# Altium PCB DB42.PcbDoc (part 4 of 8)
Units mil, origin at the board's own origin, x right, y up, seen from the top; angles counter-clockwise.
Board outline 3236.22 x 4456.69 mil, 8 copper layers (Top Layer, MidLayer1, MidLayer2, GND-Layer5, MidLayer3, VCC, MidLayer4, Bottom Layer), stack 62.194 mil thick; 214 components, 470 nets, 1802 pads, 1663 vias.
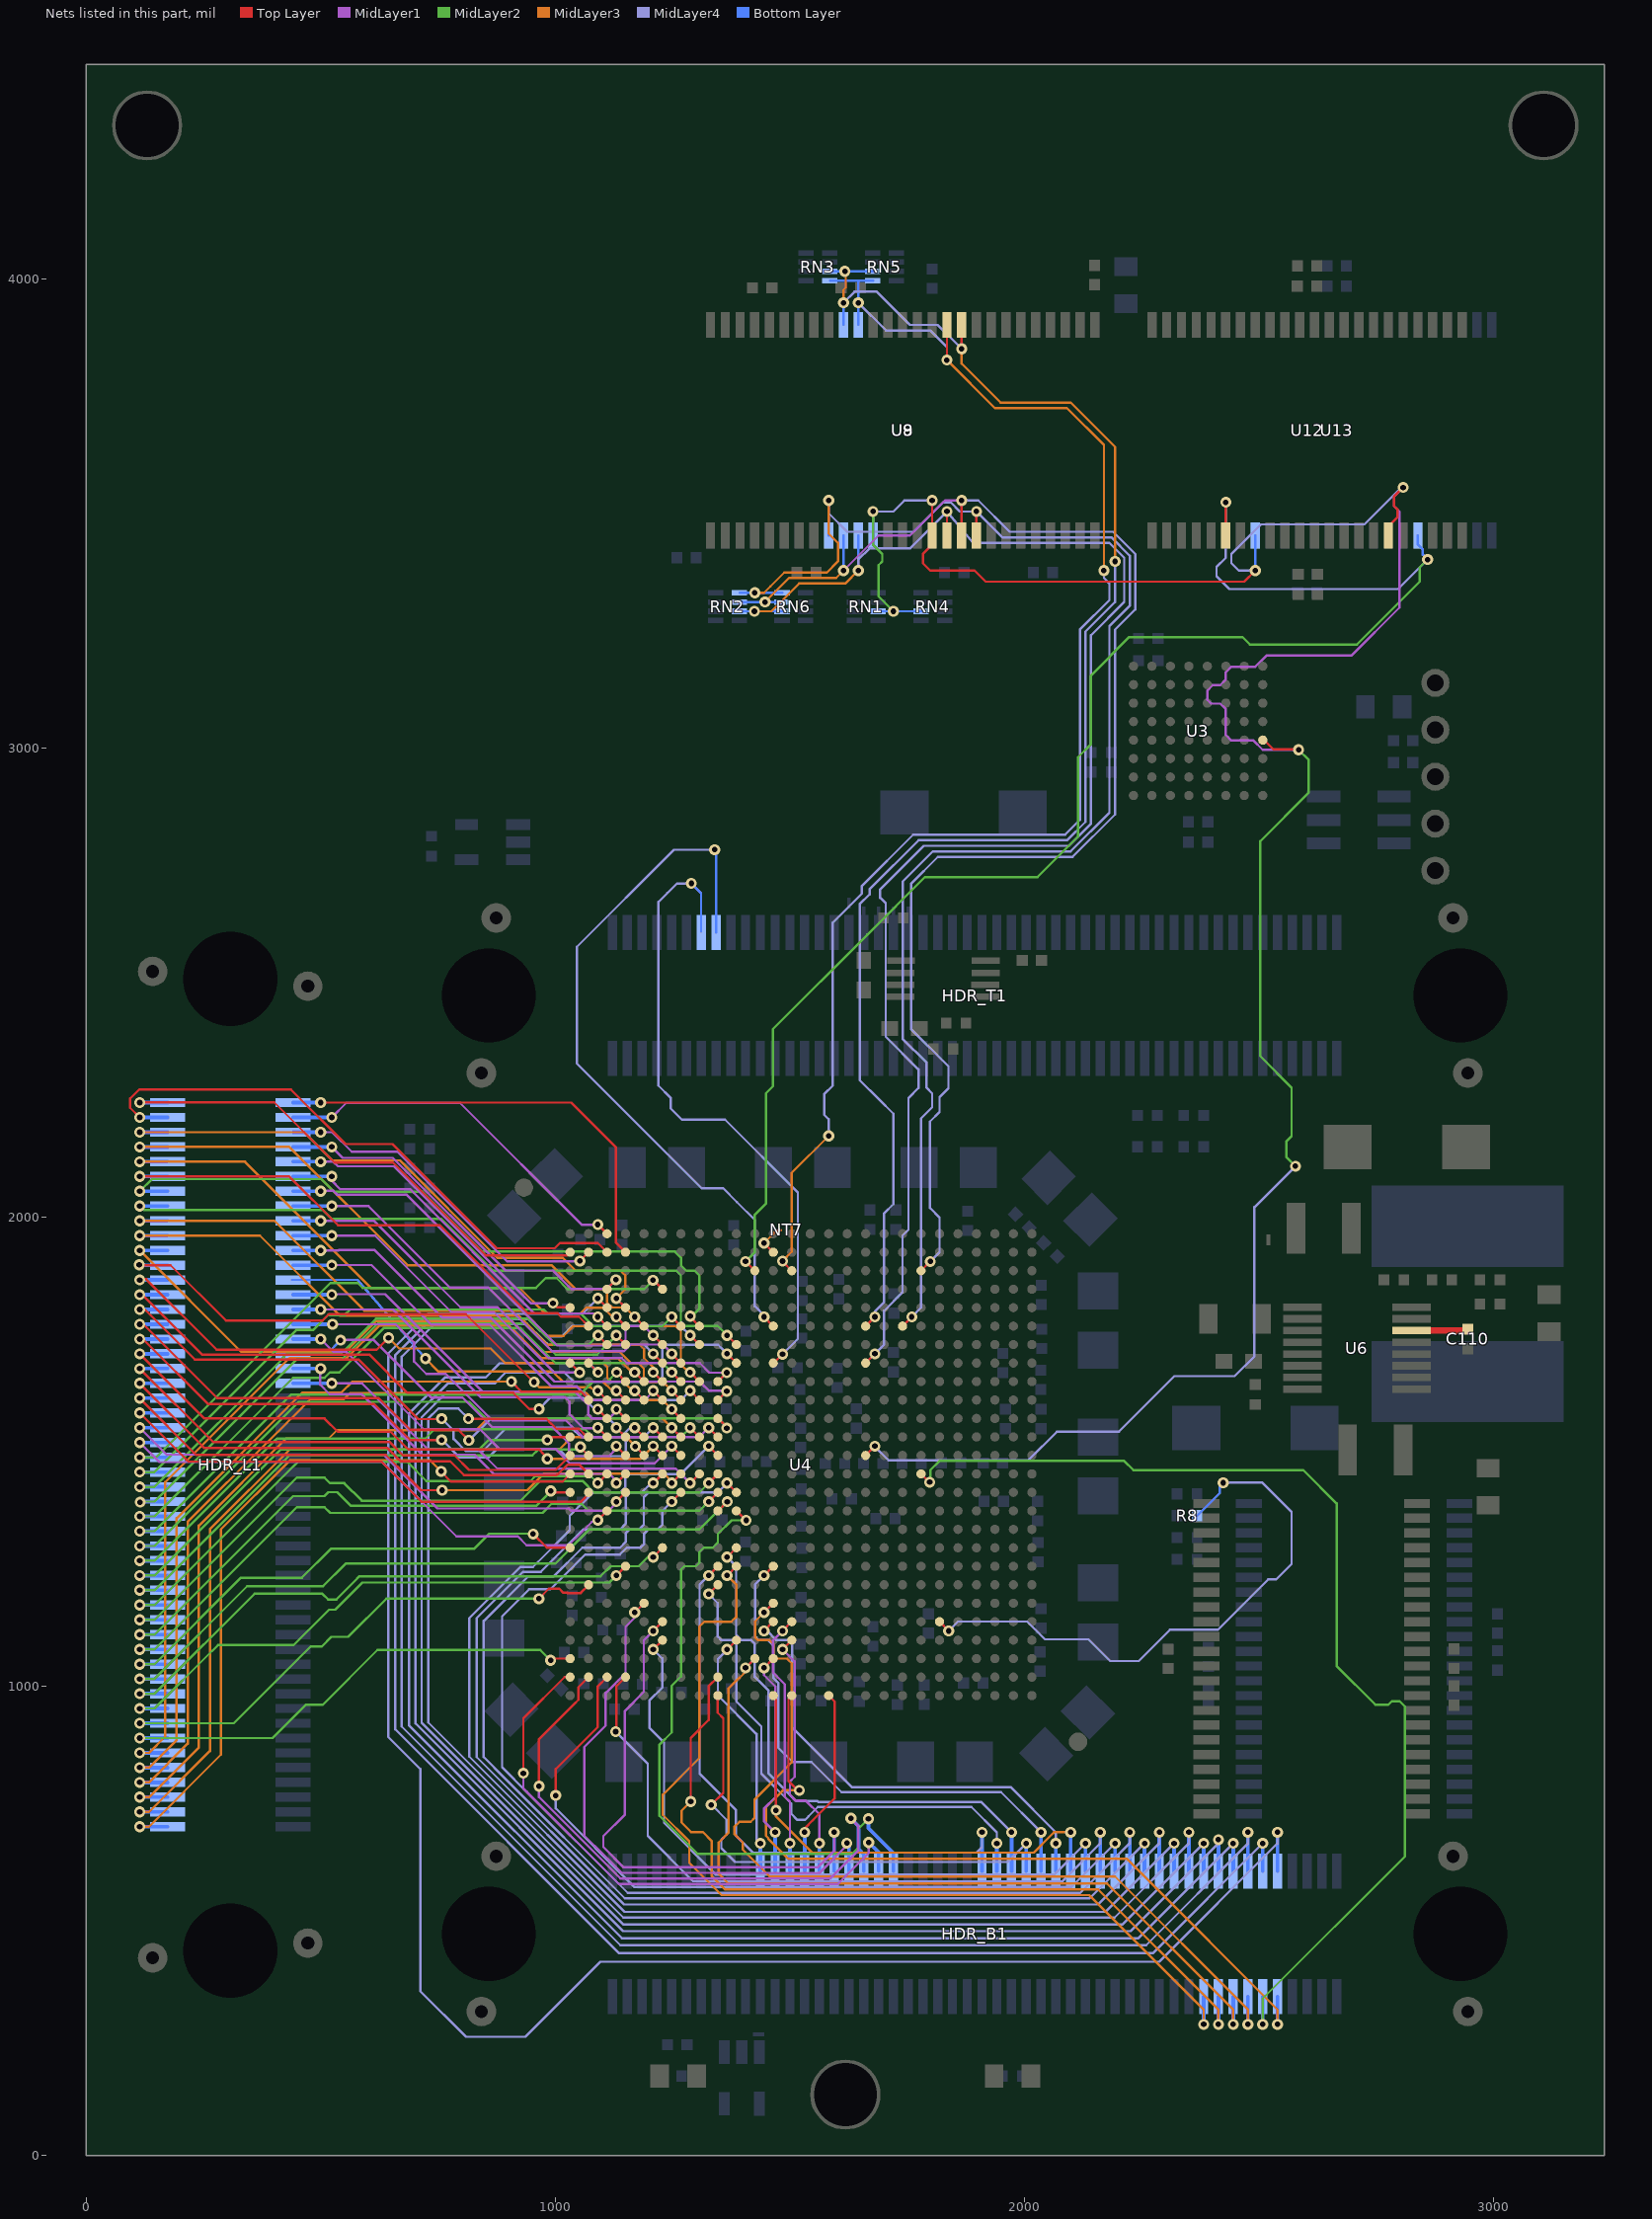
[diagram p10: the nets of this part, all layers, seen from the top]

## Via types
v1: diameter 23.62, hole 11.81, Top Layer to Bottom Layer, 1081 vias
v2: diameter 23.62, hole 11.81, Top Layer to Bottom Layer, tented both sides, 466 vias
v3: diameter 27.56, hole 15.75, Top Layer to Bottom Layer, 116 vias

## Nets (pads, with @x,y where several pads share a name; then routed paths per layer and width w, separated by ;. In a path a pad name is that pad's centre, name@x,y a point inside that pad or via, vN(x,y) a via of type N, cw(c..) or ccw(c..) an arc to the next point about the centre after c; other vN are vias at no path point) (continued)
BUS_NWE: RN1.7 RN4.6 U3.A5 U4.N17 U8.16 U9.16 U12.17 U13.17 | length 5598.1
  Top Layer w5: U4.N17@1661.42,1492.13 v1(1681.1,1511.81) ; U8.16@1803.14,3452.75 v2(1803.14,3527.55) ; U8.16@1803.15,3460.62 1803.15,3433.07 1783.46,3413.39 1783.46,3393.7 1799.21,3377.95 1893.7,3377.95 1917.32,3354.33 2468.5,3354.33 v1(2492.13,3377.95) ; U3.A5@2507.87,3016.73 2510.82,3016.74 2530.31,2997.24 v1@2583.46,2997.24 ; v1@2582.28,2998.03 v1(2584.25,2996.06) ; U12.17@2775.59,3452.76 2775.59,3472.44 2795.28,3492.13 2795.28,3507.87 2787.4,3515.75 2787.4,3535.43 v1(2807.09,3555.12)
  MidLayer1 w5: v1(2584.25,2996.06) 2507.87,2996.06 2488.19,3015.75 2440.94,3015.75 2429.13,3027.56 2429.13,3082.68 2417.32,3094.49 2397.64,3094.49 2389.76,3102.36 2389.76,3122.05 2401.57,3133.86 2417.32,3133.86 2429.13,3145.67 2429.13,3161.42 2440.94,3173.23 2492.13,3173.23 2515.75,3196.85 2696.85,3196.85 2799.21,3299.21 2799.21,3503.94 2787.4,3515.75 2787.4,3535.43 v1(2807.09,3555.12)
  MidLayer2 w5: v2(1677.17,3503.94) 1677.17,3433.07 1696.85,3413.39 1696.85,3397.64 1688.98,3389.76 1688.98,3322.83 v1(1720.47,3291.34) ; v1(2577.56,2108.66) 2557.87,2128.35 2557.87,2161.02 2569.29,2172.44 2569.29,2275.99 2502.31,2342.96 2502.31,2801.13 2605.91,2904.72 2605.91,2974.41 v1(2584.25,2996.06)
  MidLayer4 w5: v2(1677.17,3503.94) 1720.47,3503.94 1744.09,3527.55 v2(1803.14,3527.55) ; v1@1681.1,1510.69 1709.9,1481.89 2008.27,1481.89 2069.29,1542.91 2201.18,1542.91 2319.37,1661.1 2447.92,1661.1 2490.08,1703.26 2490.08,2021.18 v1(2577.56,2108.66) ; v1(2492.13,3377.95) 2456.69,3377.95 2440.94,3393.7 2440.94,3413.39 2503.94,3476.38 2724.41,3476.38 v1@2805.12,3557.09
  Bottom Layer w5: U9.16@1677.17,3452.76 v2(1677.17,3503.94) ; RN1.7@1688.18,3291.34 RN4.6@1779.53,3291.33 RN4.6@1779.92,3291.34 ; v1(2492.13,3377.95) U13.17@2492.13,3452.76
BUS_SDRAM_CKE: RN3.7 RN5.6 U4.F17 U8.37 U9.37 | length 3341.3
  Top Layer w5: U4.F17@1661.42,1767.72 v1(1681.1,1787.4) ; v2(1866.14,3850.39) U8.37@1866.14,3901.57
  MidLayer3 w5: v2(1614.17,3948.82) 1614.17,3976.38 1618.9,3981.11 v1@1618.9,4015.75 ; v2(1866.14,3850.39) 1866.14,3818.9 1948.82,3736.22 2098.43,3736.22 2192.91,3641.73 v1(2192.91,3397.64)
  MidLayer4 w5: v2(1614.17,3948.82) 1637.8,3972.44 1685.04,3972.44 1755.91,3901.57 1814.96,3901.57 v2(1866.14,3850.39) ; v1(1681.1,1787.4) 1681.1,1799.31 1700.79,1819 1700.79,1925.59 1700.89,1925.69 1700.89,2008.37 1720.47,2027.95 1720.47,2220.47 1689.76,2251.18 1648.82,2292.12 1648.82,2666.9 1669.68,2687.76 1669.68,2698.43 1774.41,2803.15 2090.55,2803.15 2129.92,2842.52 2129.92,3248.03 2192.91,3311.02 v1(2192.91,3397.64)
  Bottom Layer w5: RN3.7@1586.22,4015.75 v1(1617.14,4015.75) RN5.6@1676.19,4015.75 RN5.6@1677.56,4015.75 ; U9.37@1614.17,3901.57 v2(1614.17,3948.82)
BUS_SDRAM_CLK: NT7.2 RN3.8 RN5.5 U4.C13 U8.38 U9.38 | length 3185.7
  Top Layer w5: v1@1484.25,1905.51 U4.C13@1503.94,1885.83 ; v2(1834.64,3826.77) U8.38@1834.65,3901.57
  MidLayer1 w5: v1(1484.25,1906.3) v1@1485.43,1906.3
  MidLayer3 w5: v1(1484.25,1906.3) 1503.96,1926 1503.96,2094.47 v1(1582.68,2173.23) ; v2(1834.64,3826.77) 1937,3724.41 2090.55,3724.41 2169.29,3645.67 v1(2169.29,3377.95)
  MidLayer4 w5: v1(1582.68,2173.23) 1582.68,2208.66 1573,2218.34 1573,2262 1591.2,2280.2 1591.2,2627.42 1653.54,2689.76 1653.54,2705.91 1762.6,2814.96 2086.61,2814.96 2118.11,2846.46 2118.11,3251.97 2181.1,3314.96 2181.1,3350.39 2169.29,3362.2 v1(2169.29,3377.95) ; v2(1645.67,3948.82) 1704.72,3889.76 1799.21,3889.76 1834.64,3854.34 v2(1834.64,3826.77)
  Bottom Layer w5: RN3.8@1586.22,3996.06 RN5.5@1676.19,3996.06 RN5.5@1677.56,3996.06 ; U9.38@1645.67,3901.57 v2(1645.67,3948.82) 1645.67,3996.06
BUS_SDRAM_FEEDBACK: NT7.1 U4.B12 | length 75.8
  Top Layer w5: v1(1444.88,1944.88) U4.B12@1464.57,1925.2
  MidLayer2 w5: v1(1444.88,1944.88) v1@1445.67,1944.88
  MidLayer3 w5: v1(1444.88,1944.88) 1472.44,1972.44 NT7.1@1480.65,1972.44
BUS_SDRAM_NCAS: RN2.7 RN6.6 U4.H17 U8.17 U9.17 | length 3341.6
  Top Layer w5: U4.H17@1661.42,1688.98 v1(1681.1,1708.66) ; U8.17@1834.65,3452.76 1834.64,3499.99 v1(1834.65,3503.94)
  MidLayer3 w5: v1(1424.23,3291.34) 1460.63,3291.34 1519.68,3350.39 1618.11,3350.39 v2(1645.67,3377.95)
  MidLayer4 w5: v2(1645.67,3377.95) 1645.67,3401.57 1669.29,3425.2 1755.91,3425.2 v1(1834.65,3503.94) 1890.42,3437.01 2181.1,3437.01 2212.6,3405.51 2212.6,3311.02 2141.73,3240.16 2141.73,2838.58 2094.49,2791.34 1785.43,2791.34 1692.52,2698.43 1692.52,2680.71 1704.26,2668.96 1704.26,2384.54 1774.02,2314.78 1774.02,2275.2 1752.76,2253.94 1752.76,1973.23 1740.18,1960.65 1740.18,1905.78 ; v1@1682.28,1709.84 1700.79,1728.35 1700.79,1800.39 1740.16,1839.76 1740.16,1905.04
  Bottom Layer w5: RN2.7@1393.3,3291.34 RN6.6@1483.28,3291.34 ; v2(1645.67,3377.95) U9.17@1645.67,3452.76
BUS_SDRAM_NCS: RN2.5 RN6.8 U4.F19 U8.19 U9.19 | length 3385.9
  Top Layer w5: U4.F19@1740.16,1767.72 v1(1759.84,1787.4) ; U8.19@1897.64,3452.76 v2(1897.63,3503.93)
  MidLayer3 w5: v1(1425.2,3330.71) 1444.88,3330.71 1458.54,3344.36 1488.19,3374.02 1578.74,3374.02 1602.36,3397.64 1602.36,3437.01 1582.68,3456.69 v2(1582.68,3527.56)
  MidLayer4 w5: v2(1582.68,3527.56) 1582.68,3500 1622.05,3460.63 1763.78,3460.63 1826.77,3523.62 1842.52,3523.62 1862.21,3503.93 v2(1897.63,3503.93) 1952.76,3448.82 2185.04,3448.82 2224.41,3409.45 2224.41,3303.15 2181.1,3259.84 2181.1,2862.2 2098.43,2779.53 1804.72,2779.53 1740.3,2715.1 1740.3,2380.17 1791.34,2329.13 1791.34,2275.59 1803.15,2263.78 1803.15,2234 1779.53,2210.38 1779.53,1807.09 v1(1759.84,1787.4) v1@1759.45,1787.01
  Bottom Layer w5: RN2.5@1393.31,3330.71 v1(1425.2,3330.71) RN6.8@1483.28,3330.71 RN6.8@1484.26,3330.71 ; U9.19@1582.68,3452.76 v2(1582.68,3527.56)
BUS_SDRAM_NRAS: RN2.6 RN6.7 U4.C20 U8.18 U9.18 | length 3143.8
  Top Layer w5: U4.C20@1779.53,1885.83 v1(1799.21,1905.51) ; U8.18@1866.14,3452.76 v1(1866.14,3527.55)
  MidLayer1 w5: v2(1614.17,3377.95) 1688.98,3452.76 1755.91,3452.76 1830.7,3527.55 v1(1866.14,3527.55)
  MidLayer3 w5: v1(1446.86,3311.02) 1498.05,3362.2 1598.43,3362.2 v2(1614.17,3377.95)
  MidLayer4 w5: v1(1799.21,1905.51) 1818.9,1925.2 1818.9,1999.21 1798.43,2019.68 1798.43,2203.54 1818.9,2224.02 1818.9,2255.91 1837.88,2274.89 1837.88,2321.56 1758.27,2401.18 1758.27,2710.63 1815.35,2767.72 2102.36,2767.72 2192.91,2858.27 2192.91,3251.97 2236.22,3295.28 2236.22,3413.39 2188.98,3460.63 1968.5,3460.63 1901.58,3527.55 v1(1866.14,3527.55) v1@1858.27,3531.5
  Bottom Layer w5: RN2.6@1393.3,3311.02 v1(1446.86,3311.02) RN6.7@1483.28,3311.02 RN6.7@1484.64,3311.02 ; v2(1614.17,3377.95) U9.18@1614.17,3452.76
BUS_SRAM_NCS: U4.C11 U12.6 U13.6 | length 3357.1
  Top Layer w5: v1(1405.51,1905.51) U4.C11@1425.2,1885.83 ; U12.6@2429.13,3452.76 2429.13,3503.94 v2(2429.13,3523.62)
  MidLayer2 w5: v1(1405.51,1905.51) 1425.2,1925.2 1425.2,2005.12 1448.82,2028.74 1448.82,2244.09 1448.82,2263.78 1463.83,2278.79 1463.83,2400.84 1665.15,2602.16 ; 1664.95,2601.96 1665.15,2602.16 ; v2(2859.27,3401.57) 2842.52,3384.83 2842.52,3354.33 2708.66,3220.47 2480.32,3220.47 2464.57,3236.22 2223.42,3236.22 2141.73,3154.53 2141.73,3007.87 2114.17,2980.32 2114.17,2811.02 2027.56,2724.41 1787.4,2724.41 1665.15,2602.16
  MidLayer4 w5: v2(2429.13,3523.62) 2429.13,3405.51 2409.45,3385.83 2409.45,3366.14 2437.01,3338.58 2796.28,3338.58 v2(2859.27,3401.57)
  Bottom Layer w5: U13.6@2838.58,3452.76 2838.58,3433.42 2848.92,3423.08 2848.92,3411.92 v2(2859.27,3401.57)
BUZZER: HDR_B1.40 U4.T10 | length 1446.8
  Top Layer w5: U4.T10@1385.83,1374.02 1386.61,1374.02 v1(1406.69,1353.94)
  MidLayer2 w5: v1(1406.69,1353.94) 1375.59,1353.94 1346.46,1324.8 1346.46,1306.3 1335.43,1295.27 1316.14,1295.27 1307.09,1286.22 1307.09,1263.39 1299.77,1256.07 1274.58,1256.07 1268.09,1249.59 1268.09,1021.09 1248,1001 1248,902 1222,876 1222,724 1303.09,642.91 1632.68,642.91 1645.28,655.51 1645.28,695.67 v2(1667.32,717.72)
  Bottom Layer w7.87: v2(1667.32,717.72) 1667.32,697.64 1720.47,644.49 HDR_B1.40@1720.47,606.3
CAN_RXD: HDR_T1.14 U4.H12 | length 1378.5
  Top Layer w5: U4.H12@1464.57,1688.98 1465.35,1688.98 v1(1484.25,1707.87)
  MidLayer4 w5: v1@1288.98,2711.02 1259.06,2711.02 1238.95,2690.92 1219.68,2671.65 1219.68,2280.31 1245.67,2254.32 1245.67,2231.89 1269.69,2207.87 1361.81,2207.87 1516.93,2052.76 1516.93,1740.55 v1(1484.25,1707.87)
  Bottom Layer w5: v1(1289.76,2711.42) 1310.63,2690.55 HDR_T1.14@1310.63,2609.06
CAN_TXD: HDR_T1.16 U4.F12 | length 1562.1
  Top Layer w5: v1(1444.88,1787.4) U4.F12@1464.57,1767.72
  MidLayer4 w5: v1(1339.76,2783.07) 1253.15,2783.07 1046.06,2575.98 1046.06,2327.17 1311.71,2061.52 1357.77,2061.52 1387.13,2032.16 1425.2,1994.09 1425.2,1810.24 1444.88,1790.55 v1(1444.88,1787.4)
  Bottom Layer w5: HDR_T1.16@1342.52,2606.3 v1@1342.52,2780.32
COMP: C110.2 U6.6 | length 121.4
  Top Layer w13.78: U6.6@2824.58,1758.25 2942.3,1758.25 C110.2@2944.88,1760.82
DAU_RESET_SW: HDR_B1.38 U4.AE1 | length 1225.8
  Top Layer w5: v1(931.85,814.75) 931.85,931.72 1019.81,1019.68 U4.AE1@1031.5,1019.68
  MidLayer1 w5: v1(931.85,814.75) 931.85,782.28 1135.39,578.74 1602.36,578.74 1661.24,637.61 1668.11,644.49 v2(1668.11,667.32)
  Bottom Layer w7.87: v2(1668.11,667.32) 1688.98,646.46 HDR_B1.38@1688.98,606.3
DAU_TFT_BLIGHT: HDR_B1.91 U4.AF13 | length 1698.6
  Top Layer w5: U4.AF13@1503.94,980.31 1496.85,973.23 1496.85,798.43 1516.93,778.35 v1(1520.08,778.35)
  MidLayer3 w5: v1(1520.08,778.35) 1485.22,778.35 1449,742.13 1449,681.27 1453.73,676.54 1453.73,675.01 1496.06,632.68 2218.11,632.68 2251.57,599.21 ; 2251.38,599.02 2539.37,311.02 v2(2539.37,279.53)
  Bottom Layer w7.87: v2(2539.37,279.53) HDR_B1.91@2539.37,338.58
DAU_TFT_BLUE0: HDR_B1.62 U4.AB12 | length 1014.6
  Top Layer w5: v1(1444.88,1118.11) U4.AB12@1464.57,1137.8
  MidLayer4 w5: v1(1444.88,1118.11) 1451.58,1118.11 1471.26,1098.43 1496.85,1098.43 1504.54,1090.74 1504.54,912.79 1539.37,877.95 ; 1539.37,877.95 1542.25,875.06 1632.68,784.65 1971.26,784.65 2066.93,688.98 v2(2066.93,665.35)
  Bottom Layer w7.87: HDR_B1.62@2066.93,606.3 v2(2066.93,665.35)
DAU_TFT_BLUE1: HDR_B1.64 U4.AF12 | length 1020.7
  Top Layer w5: U4.AF12@1464.57,980.31 1470.47,974.41 v1(1470.47,735.83)
  MidLayer3 w5: v1(1470.47,735.83) 1470.47,722.44 1506.16,686.75 1547.24,645.67 2019.69,645.67 2055.88,681.86 2062.99,688.98 v2(2098.42,688.98)
  Bottom Layer w7.87: v2(2098.42,688.98) HDR_B1.64@2098.43,606.3
DAU_TFT_BLUE2: HDR_B1.66 U4.AC6 | length 1460.6
  Top Layer w5: v1(1208.66,1078.74) U4.AC6@1228.35,1098.42
  MidLayer4 w5: v1(1208.66,1078.74) 1227.97,1059.43 1227.97,997.26 1200.39,969.68 1200.39,911.61 1231.66,880.34 1231.66,709.29 1342.52,598.43 2062.99,598.43 v2(2129.92,665.35)
  Bottom Layer w7.87: HDR_B1.66@2129.92,606.3 v2(2129.92,665.35)
DAU_TFT_BLUE3: HDR_B1.68 U4.AE4 | length 1520.6
  Top Layer w5: v1(1128.65,903.31) 1130.19,904.86 1130.19,965.58 1130.16,1000.24 ; 1129.92,1000 1130.16,1000.24 ; 1130.16,1000.71 1130.16,1000.24 ; U4.AE4@1149.61,1019.68 1130.16,1000.24
  MidLayer4 w5: v1(1128.65,903.31) 1196.96,835 1196.96,714.47 1196.91,681.04 1293.31,584.65 2080.71,584.65 2161.42,665.35 v2(2161.42,688.98)
  Bottom Layer w7.87: HDR_B1.68@2161.42,606.3 v2(2161.42,688.98)
DAU_TFT_BLUE4: HDR_B1.70 U4.AE3 | length 1683.9
  Top Layer w5: v1(1000.73,767.52) 1000.73,823.61 1090.55,913.43 1090.55,1000 U4.AE3@1110.24,1019.68
  MidLayer4 w5: v1(1000.73,767.52) 1000.73,739.97 1167.86,572.83 2100.39,572.83 v2(2192.91,665.35)
  Bottom Layer w7.87: HDR_B1.70@2192.91,606.3 v2(2192.91,665.35)
DAU_TFT_CL1: HDR_B1.88 U4.H6 | length 3600.2
  Top Layer w5: v1(1208.66,1708.66) U4.H6@1228.35,1688.98
  MidLayer4 w5: 975.45,1736.68 939.84,1772.28 742.36,1772.28 672.44,1702.36 672.44,914.56 1138.57,448.43 2259.45,448.43 2476.38,665.35 v2(2476.38,688.98) ; 975.68,1736.91 984.25,1728.35 1188.98,1728.35 v1(1208.66,1708.66)
  Bottom Layer w7.87: HDR_B1.88@2476.38,606.3 v2(2476.38,688.98)
DAU_TFT_CL2: HDR_B1.90 U4.G8 | length 3780
  Top Layer w5: v1(1287.4,1748.03) U4.G8@1307.09,1728.35
  MidLayer4 w5: v1(1287.4,1748.03) 1267.72,1767.71 1035.41,1767.71 1013.26,1745.56 980.71,1745.56 943.99,1782.28 735.04,1782.28 659.06,1706.3 659.06,908.07 1136.02,431.1 2273.62,431.1 v2(2507.87,665.35)
  Bottom Layer w7.87: v2(2507.87,665.35) HDR_B1.90@2507.88,606.3 v2(2507.87,665.35)
DAU_TFT_CL3: HDR_B1.92 U4.E3 | length 4055.1
  Top Layer w5: v1(1090.55,1826.77) U4.E3@1110.24,1807.09
  MidLayer4 w5: 754.71,1793.7 728.35,1793.7 643.7,1709.06 643.7,892.3 712.2,823.8 712.2,350.39 809.65,252.95 936.02,252.95 1096.06,412.99 2287.01,412.99 2539.37,665.35 v2(2539.37,688.98) ; 754.72,1793.69 1057.47,1793.69 v1(1090.55,1826.77)
  Bottom Layer w7.87: HDR_B1.92@2539.37,606.3 v2(2539.37,688.98)
DAU_TFT_DISP_ON: HDR_B1.89 U4.P20 | length 2363.5
  Top Layer w5: U4.P20@1779.53,1452.76 v1@1799.21,1433.07
  MidLayer2 w5: v1@1799.21,1433.07 1799.21,1460.63 1818.9,1480.32 2212.6,1480.32 2232.28,1460.63 2594.49,1460.63 2665.35,1389.76 2665.35,1043.31 2748.03,960.63 2775.59,960.63 2783.46,968.5 2799.21,968.5 2811.02,956.69 2811.02,637.8 2507.88,334.65 v2(2507.88,279.53)
  Bottom Layer w7.87: v2(2507.88,279.53) HDR_B1.89@2507.88,338.58
  other v1: 1798,1435
DAU_TFT_GREEN0: HDR_B1.72 U4.R7 | length 2441
  Top Layer w5: v1(1248.03,1393.7) U4.R7@1267.72,1413.39
  MidLayer4 w5: v1(1248.03,1393.7) 1227.97,1373.64 1227.97,1344.51 1217.73,1334.27 1198.03,1334.27 1189.35,1325.59 1189.35,1303.52 1181.48,1295.65 1152.31,1295.65 1137.37,1280.71 1063.39,1280.71 989.37,1206.69 943.96,1206.69 886.58,1149.31 886.58,827.54 939.49,774.63 1154.29,559.84 2118.9,559.84 2224.41,665.36 v2(2224.41,688.98)
  Bottom Layer w7.87: HDR_B1.72@2224.41,606.3 v2(2224.41,688.98)
DAU_TFT_GREEN1: HDR_B1.74 U4.R10 | length 2644.9
  Top Layer w5: v1(1366.14,1433.07) U4.R10@1385.83,1413.39
  MidLayer4 w5: v1(1366.14,1433.07) 1346.46,1413.38 1198.82,1413.38 1188.6,1403.16 1188.6,1344.49 1179.13,1335.02 1158.25,1335.02 1152.62,1329.4 1149.98,1326.75 1149.98,1307.46 1137.8,1295.28 1057.48,1295.28 996.06,1233.86 941.7,1233.86 847.31,1139.47 847.31,849.11 890.61,805.8 1147.99,548.43 2138.97,548.43 v2(2255.9,665.35)
  Bottom Layer w7.87: HDR_B1.74@2255.91,606.3 v2(2255.9,665.35)
DAU_TFT_GREEN2: HDR_B1.76 U4.P6 | length 2597.7
  Top Layer w5: v1(1208.66,1433.07) U4.P6@1228.35,1452.76
  MidLayer4 w5: v1(1208.66,1433.07) 1208.27,1432.68 1203.97,1432.68 1184.68,1413.38 1160.63,1413.38 1153.45,1406.2 1149.98,1402.74 1149.98,1346.46 1137.79,1334.27 1059.47,1334.27 969.29,1244.1 931.18,1244.1 832.46,1145.38 832.46,849.24 1146.66,535.04 2157.09,535.04 2287.4,665.35 v2(2287.4,688.98)
  Bottom Layer w7.87: HDR_B1.76@2287.4,606.3 v2(2287.4,688.98)
DAU_TFT_GREEN3: HDR_B1.78 U4.N9 | length 2773
  Top Layer w5: v1(1326.77,1511.81) U4.N9@1346.46,1492.13
  MidLayer4 w5: v1(1326.77,1511.81) 1267.47,1452.51 1158.02,1452.51 1149.23,1443.72 1149.23,1424.84 1137.4,1413.01 1079.9,1413.01 1030.71,1363.82 1030.71,1332.68 962.76,1264.73 952.36,1254.33 925.68,1254.33 816.72,1145.38 816.72,850.18 1147.6,519.29 2172.83,519.29 v2(2318.9,665.35)
  Bottom Layer w7.87: HDR_B1.78@2318.9,606.3 v2(2318.9,665.35)
DAU_TFT_GREEN4: HDR_B1.80 U4.M2 | length 2993.6
  Top Layer w5: v1(814.75,1570.46) 980.67,1570.46 991.85,1559.29 ; 988.41,1562.73 1002.24,1548.9 1050.08,1548.9 1067.48,1531.5 U4.M2@1070.87,1531.5
  MidLayer4 w5: 729,1083.38 729,1570.32 750.79,1592.11 793.1,1592.11 v1(814.75,1570.46) ; 729.14,1083.38 729.14,922.99 1145.05,507.09 2192.13,507.09 2350.39,665.35 v2(2350.39,688.98)
  Bottom Layer w7.87: HDR_B1.80@2350.4,606.3 v2(2350.39,688.98)
DAU_TFT_GREEN5: HDR_B1.82 U4.K8 | length 3265.7
  Top Layer w5: v1(1287.4,1629.92) U4.K8@1307.09,1610.24
  MidLayer4 w5: v1(1287.4,1629.92) 1267.71,1610.23 1078.46,1610.23 1060.22,1628.48 770.06,1628.48 715,1573.42 715,922.42 1145.3,492.13 2208.66,492.13 v2(2381.89,665.35)
  Bottom Layer w7.87: HDR_B1.82@2381.89,606.3 v2(2381.89,665.35)
DAU_TFT_IRQ: HDR_B1.81 U4.W10 | length 2087.6
  Top Layer w5: v1(1366.14,1236.22) U4.W10@1385.83,1255.91
  MidLayer3 w5: v1(1366.14,1236.22) 1386.2,1216.16 1386.2,1148.4 1375.22,1137.42 1316.95,1137.42 1307.09,1127.56 1307.09,847.09 1229,769 1229,726.12 1285.43,669.69 1285.43,624.02 1354.33,555.12 2137.8,555.12 2381.89,311.02 v2(2381.89,279.53)
  Bottom Layer w7.87: v2(2381.89,279.53) HDR_B1.81@2381.89,338.58
DAU_TFT_M: HDR_B1.87 U4.AA12 | length 1981.1
  Top Layer w5: v1(1444.88,1157.48) U4.AA12@1464.57,1177.17
  MidLayer3 w5: v1(1444.88,1157.48) 1428.1,1140.7 1425.57,1138.17 1425.57,1104.35 1431.5,1098.43 1456.3,1098.43 1464.57,1090.16 1464.57,1068.11 1473.62,1059.06 1494.09,1059.06 1503.84,1049.31 1503.84,837.84 1424.41,758.41 1424.41,719.29 1416.54,711.42 1392.52,711.42 1381.5,700.39 1381.5,685.43 1399.61,667.32 1399.61,651.97 1457.09,594.49 2192.91,594.49 2476.38,311.02 v2(2476.38,279.53)
  Bottom Layer w7.87: v2(2476.38,279.53) HDR_B1.87@2476.38,338.58
DAU_TFT_MUX: HDR_B1.85 U4.AD11 | length 1797.5
  Top Layer w5: v1(1405.51,1039.37) U4.AD11@1425.2,1059.05
  MidLayer3 w5: 1393,1019 1368.83,994.83 1368.83,687.73 1348.43,667.32 1348.43,600.39 1368.9,579.92 2175.98,579.92 2444.88,311.02 v2(2444.88,279.53) ; 1393.2,1018.8 1405.51,1031.1 v1(1405.51,1039.37)
  Bottom Layer w7.87: v2(2444.88,279.53) HDR_B1.85@2444.88,338.58
DAU_TFT_POL: HDR_B1.83 U4.AE9 | length 1786.2
  Top Layer w5: v1@1288,754 v1@1288,754.33 ; v1(1288.58,754.33) 1288.58,890.06 1326.77,928.25 1326.77,1000 U4.AE9@1346.46,1019.68
  MidLayer3 w5: v1(1288.58,754.33) 1269.06,734.8 1269.06,709.68 1289.2,689.54 1314.39,689.54 1332.97,670.97 1332.97,596.16 1362.2,566.93 2157.48,566.93 2413.39,311.03 v2(2413.39,279.53)
  Bottom Layer w7.87: v2(2413.39,279.53) HDR_B1.83@2413.39,338.58
DAU_TFT_RED0: HDR_B1.52 U4.W9 | length 1280.8
  Top Layer w5: v1(1326.77,1236.22) U4.W9@1346.46,1255.91
  MidLayer4 w5: v1(1326.77,1236.22) 1307.46,1216.91 1307.46,814.09 1384.55,737 1384.55,682.38 1410.96,655.97 1421.26,645.67 1897.64,645.67 1909.45,657.48 v2(1909.45,688.98)
  Bottom Layer w7.87: HDR_B1.52@1909.45,606.3 v2(1909.45,688.98)
DAU_TFT_RED1: HDR_B1.54 U4.Y9 | length 1159.8
  Top Layer w5: v1(1326.77,1196.85) U4.Y9@1346.46,1216.54
  MidLayer4 w5: v1(1326.77,1196.85) 1346.08,1177.54 1346.08,1106.28 1353.94,1098.43 1376.77,1098.43 1385.83,1089.37 1385.83,967.72 1439,914.54 1439,814.15 1502.76,750.39 1502.76,728.74 1516.14,715.35 1532.28,715.35 1539.76,722.83 ; 1539.7,722.9 1559.71,742.91 1885.04,742.91 ; 1867.63,742.92 1887,742.92 1940.94,688.98 v2(1940.94,665.35)
  Bottom Layer w7.87: HDR_B1.54@1940.95,606.3 v2(1940.94,665.35)
DAU_TFT_RED2: HDR_B1.56 U4.V10 | length 1190
  Top Layer w5: v1(1366.14,1275.59) U4.V10@1385.83,1295.28
  MidLayer4 w5: v1(1366.14,1275.59) 1385.45,1256.28 1385.45,1110.22 1397.24,1098.43 1417.32,1098.43 1425.2,1090.55 1425.2,1020.08 1454.72,990.55 1454.72,814.17 1512.99,755.91 1558.66,755.91 1561.42,753.15 1908.27,753.15 v2(1972.44,688.98)
  Bottom Layer w7.87: HDR_B1.56@1972.44,606.3 v2(1972.44,688.98)
DAU_TFT_RED3: HDR_B1.58 U4.AF9 | length 1100.1
  Top Layer w5: v1@1330.71,745.67 v1(1332.44,747.4) 1357.94,772.9 1357.94,932.06 1346,944 1346,980.31 1346,980.68 U4.AF9@1346.04,980.73
  MidLayer4 w5: v1(1332.44,747.4) 1333.31,747.4 1364.96,715.75 1364.96,683.86 1353.94,672.83 1353.94,654.72 1383.07,625.59 1964.17,625.59 v2(2003.94,665.35)
  Bottom Layer w7.87: HDR_B1.58@2003.94,606.3 v2(2003.94,665.35)
DAU_TFT_RED4: HDR_B1.60 U4.W12 | length 1152.5
  Top Layer w5: v1(1444.88,1236.22) U4.W12@1464.57,1255.91
  MidLayer4 w5: v1(1444.88,1236.22) 1425.57,1216.91 1425.57,1106.3 1433.44,1098.43 1453.15,1098.43 1464.57,1087.01 1464.57,1018.11 1475.2,1007.48 1475.2,869.29 1505.91,838.58 1546.06,838.58 1610.14,774.51 1949.9,774.51 v2(2035.43,688.98)
  Bottom Layer w7.87: HDR_B1.60@2035.43,606.3 v2(2035.43,688.98)
DAU_TFT_STH: HDR_B1.86 U4.H2 | length 3235
  Top Layer w5: U4.H2@1071.39,1688.98 v1(1090.99,1669.38)
  MidLayer4 w5: v1(1090.99,1669.38) 1071.77,1688.59 881.66,1688.59 851.26,1658.19 764.71,1658.19 688,1581.47 688,917 1141.61,463.39 2242.91,463.39 v2(2444.88,665.35)
  Bottom Layer w7.87: HDR_B1.86@2444.88,606.3 v2(2444.88,665.35)
DAU_TFT_STV: HDR_B1.84 U4.H10 | length 3510.4
  Top Layer w5: v1(1366.14,1708.66) U4.H10@1385.83,1688.98
  MidLayer4 w5: 1347.03,1727.97 1236.96,1727.97 1228.03,1719.05 1228.03,1657.06 1220.26,1649.28 1038.58,1649.28 1018.57,1669.29 894.46,1669.29 870.83,1645.67 770.89,1645.67 702,1576.78 702,921 1144.65,478.35 2226.38,478.35 v1@2413.38,665.35 ; 1347.1,1727.9 1355.95,1719.05 ; 1355.85,1718.95 v1(1366.14,1708.66)
  Bottom Layer w7.87: HDR_B1.84@2413.39,606.3 v1(2413.39,673.23)
DIP0: HDR_B1.22 U4.AC10 | length 547.2
  Top Layer w5: v1(1366.14,1078.74) U4.AC10@1385.83,1098.42
  MidLayer4 w5: v1@1366.14,1077.95 1346.46,1058.27 1346.46,980.71 1428.77,898.4 1428.77,673.59 v2(1437.01,665.35) ; v2@1437.1,666.05 1437.4,665.75 v2@1438.58,664.57
  Bottom Layer w7.87: HDR_B1.22@1437.01,606.3 v2(1437.01,665.35)
DIP1: HDR_B1.24 U4.AD12 | length 491
  Top Layer w5: v1(1444.88,1039.37) U4.AD12@1464.57,1059.05
  MidLayer1 w5: v1(1444.88,1039.37) 1444.88,1024 1469,999.88 1469,764 1444.49,739.49 1444.49,712.99 v2(1468.5,688.98)
  Bottom Layer w7.87: HDR_B1.24@1468.5,606.3 v2(1468.5,688.98)
DIP2: HDR_B1.26 U4.AB13 | length 562.8
  Top Layer w5: v1(1484.25,1118.11) U4.AB13@1503.94,1137.8
  MidLayer1 w5: v1(1484.25,1118.11) 1464.19,1098.05 1464.19,1029.13 1489,1004.33 1489,764.94 1500,753.94 v2(1500,665.35)
  Bottom Layer w7.87: HDR_B1.26@1500,606.3 v2(1500,665.35)
DIP3: HDR_B1.28 U4.AF15 | length 405.8
  Top Layer w5: v2(1531.5,688.98) 1531.5,697.16 1549.06,714.72 1595.47,761.14 1595.47,768.55 1595.47,967.52 U4.AF15@1582.68,980.31
  Bottom Layer w7.87: HDR_B1.28@1531.5,606.3 v2(1531.5,688.98)
DIP4: HDR_B1.30 U4.AC13 | length 554
  Top Layer w5: v1(1484.25,1078.74) U4.AC13@1503.94,1098.42
  MidLayer1 w5: v1(1484.25,1078.74) 1510,1052.99 1510,807 1500,797 1500,768.11 1511.81,756.3 1533.7,756.3 1562.99,727.01 v2(1562.99,665.35)
  Bottom Layer w7.87: HDR_B1.30@1562.99,606.3 v2(1562.99,665.35)
DIP5: HDR_B1.32 U4.AB6 | length 1179.2
  Top Layer w5: v1(1208.66,1118.11) U4.AB6@1228.35,1137.8
  MidLayer1 w5: v1(1208.66,1118.11) 1188.6,1098.05 1188.6,988 1148.32,947.72 1148.32,726.88 1102.36,680.93 1102.36,657.59 1145.78,614.17 1559.06,614.17 1594.49,649.61 v2(1594.49,688.98)
  Bottom Layer w7.87: HDR_B1.32@1594.49,606.3 v2(1594.49,688.98)
DIP6: HDR_B1.34 U4.AA5 | length 1231.5
  Top Layer w5: v1(1169.29,1157.48) U4.AA5@1188.98,1177.17
  MidLayer1 w5: 1102.08,641.57 1061.74,681.91 1061.74,870.84 1107.45,916.55 1107.45,985.8 1149.61,1027.95 1149.61,1127.15 1169.29,1146.83 v1(1169.29,1157.48) ; 1102.26,641.74 1141.64,602.36 1562.99,602.36 1623.82,663.19 v2@1625.98,665.35
  Bottom Layer w7.87: v2@1620.87,664.57 1625.98,659.45 HDR_B1.34@1625.99,606.3
  other v2: 1621.26,665.75
DIP7: HDR_B1.36 U4.AE2 | length 1275.3
  Top Layer w5: v1(965.3,787.2) 965.3,887.57 1040.09,962.35 ; 1040.26,962.18 1049.29,971.21 1049.29,998.11 U4.AE2@1070.87,1019.68
  MidLayer1 w5: v1(965.3,787.2) 965.3,763.82 1138.58,590.55 1586.61,590.55 1645.67,649.61 1645.67,702.76 v2(1629.92,718.5)
  Bottom Layer w7.87: v2(1629.92,718.5) 1646.46,701.97 1646.46,653.15 1657.48,642.13 HDR_B1.36@1657.48,606.3
DONE: R8.2 U4.AB21 | length 1263.8
  Top Layer w5: U4.AB21@1818.9,1137.8 v1(1838.58,1118.11)
  MidLayer4 w5: v1(1838.58,1118.11) 1858.61,1138.14 2005.74,1138.14 2043.77,1100.11 2136.26,1100.11 2182.51,1053.86 2243.52,1053.86 2310.02,1120.37 2412.1,1120.37 2519.68,1227.95 2536.61,1227.95 2569.29,1260.63 2569.29,1371.6 2506.25,1434.65 2424.65,1434.65 v1(2423.7,1433.7)
  Bottom Layer w5: R8.2@2367.64,1363.63 2416.43,1412.42 2416.43,1426.43 v1(2423.7,1433.7)
EXTEND_A0: HDR_L1.1 U4.B1 | length 1113.7
  Top Layer w5: v2@114.7,2244.62 400.85,2244.62 529.29,2116.17 654.04,2116.17 851.71,1918.5 1024.8,1918.5 U4.B1@1031.5,1925.2
  Bottom Layer w7.87: v2(114.17,2244.09) HDR_L1.1@173.23,2244.09
EXTEND_A1: HDR_L1.3 U4.B3 | length 1285.2
  Top Layer w5: v2(114.17,2212.6) 93.77,2233 93.77,2252.89 113.08,2272.2 436.45,2272.2 552.79,2155.86 653.19,2155.86 875.3,1933.75 998.79,1933.75 1009.92,1944.88 1090.55,1944.88 U4.B3@1110.24,1925.2
  Bottom Layer w7.87: v2(114.17,2212.6) HDR_L1.3@173.23,2212.6
EXTEND_A2: HDR_L1.5 U4.E4 | length 1305.2
  Top Layer w5: v1(1129.92,1826.77) U4.E4@1149.61,1807.09
  MidLayer3 w5: v2(114.17,2181.1) 464.61,2181.1 524.81,2120.9 668.47,2120.9 876.38,1912.99 1016.14,1912.99 1042.91,1886.22 1138.98,1886.22 1148.82,1876.38 1148.82,1845.67 v1(1129.92,1826.77)
  Bottom Layer w7.87: v2(114.17,2181.1) HDR_L1.5@173.23,2181.1
EXTEND_A3: HDR_L1.7 U4.F5 | length 1305
  Top Layer w5: v1(1169.29,1787.4) U4.F5@1188.98,1767.72
  MidLayer3 w5: v2(114.17,2149.61) 433.06,2149.61 685.03,1897.64 992.13,1897.64 1043.09,1846.68 1103.59,1846.68 1110.29,1839.98 1110.29,1817.92 1120.93,1807.28 1149.3,1807.28 1169.17,1787.4 v1(1169.29,1787.4)
  Bottom Layer w7.87: v2(114.17,2149.61) HDR_L1.7@173.23,2149.6
EXTEND_A4: HDR_L1.9 U4.F4 | length 1249.5
  Top Layer w5: v1(1129.92,1787.4) U4.F4@1149.61,1767.72
  MidLayer3 w5: v2(114.17,2118.11) 338.48,2118.11 608.01,1848.58 ; 608.41,1848.97 924,1848.97 978.3,1794.67 1053.56,1794.67 1065.77,1806.88 1102.41,1806.88 1121.89,1787.4 v1(1129.92,1787.4)
  Bottom Layer w7.87: v2(114.17,2118.11) HDR_L1.9@173.23,2118.11
EXTEND_A5: HDR_L1.11 U4.F2 | length 1150
  Top Layer w5: v2(114.17,2086.62) 433.01,2086.62 537.02,1982.61 754.12,1982.61 941.61,1795.12 1004.76,1795.12 1012.01,1787.87 1050.35,1787.87 1070.69,1767.54 1072.13,1766.1 U4.F2@1072.36,1766.1
  Bottom Layer w7.87: v2(114.17,2086.62) HDR_L1.11@173.23,2086.61
EXTEND_A6: HDR_L1.13 U4.F8 | length 1480.7
  Top Layer w5: v1@1287.4,1787.4 U4.F8@1307.09,1767.72
  MidLayer2 w5: v2(114.17,2055.12) 140.16,2081.11 501.56,2081.11 528.75,2053.92 717.73,2053.92 845.19,1926.46 1255.09,1926.46 1256.86,1924.69 ; 1256.66,1924.49 1267.69,1913.46 1267.69,1897.31 1279.32,1885.68 1297.05,1885.68 1307.27,1875.46 1307.27,1805.29 v1@1289.56,1787.58
  Bottom Layer w7.87: v2(114.17,2055.12) HDR_L1.13@173.23,2055.12
  other v1: 1287.59,1788.76
EXTEND_A7: HDR_L1.15 U4.G10 | length 1511.6
  Top Layer w5: v1(1366.14,1748.03) U4.G10@1385.83,1728.35
  MidLayer2 w5: v2(114.17,2023.62) 122.49,2015.31 504.32,2015.31 522.44,1997.19 522.44,1996.4 756.87,1996.4 867.19,1886.08 1257.62,1886.08 1267.5,1876.2 1267.5,1776.94 1276.56,1767.88 1346.3,1767.88 v1(1366.14,1748.03)
  Bottom Layer w7.87: v2(114.17,2023.62) HDR_L1.15@173.23,2023.62
EXTEND_A8: HDR_L1.17 U4.J8 | length 1452.6
  Top Layer w5: v1(1287.4,1669.29) U4.J8@1307.09,1649.61
  MidLayer3 w5: v2(114.17,1992.13) 401.42,1992.13 592.76,1800.79 930.07,1800.79 983.86,1747 1017.63,1747 1038.12,1767.48 1257.33,1767.48 1262.47,1762.34 1267.5,1757.24 1267.5,1685.93 1284.13,1669.29 v1(1287.4,1669.29)
  Bottom Layer w7.87: v2(114.17,1992.13) HDR_L1.17@173.23,1992.12
EXTEND_A9: HDR_L1.19 U4.J6 | length 1319.5
  Top Layer w5: v1(1208.66,1669.29) U4.J6@1228.35,1649.61
  MidLayer3 w5: v2(114.17,1960.63) 370.27,1960.63 540.48,1790.43 921.12,1790.43 983.46,1728.08 1179.64,1728.08 1189.09,1718.63 1189.09,1699.72 1208.66,1680.15 v1(1208.66,1669.29)
  Bottom Layer w7.87: v2(114.17,1960.63) HDR_L1.19@173.23,1960.63
EXTEND_A10: HDR_L1.21 U4.K7 | length 1411.3
  Top Layer w5: v1(1248.03,1629.92) U4.K7@1267.72,1610.24
  MidLayer3 w5: v2(114.17,1929.13) 330.59,1712.72 552.09,1712.72 618.11,1778.74 906.3,1778.74 972.32,1712.72 1137.48,1712.72 1161.12,1689.08 1176.88,1689.08 1188.7,1677.26 1188.7,1657.95 1197.37,1649.28 1228.67,1649.28 v1(1248.03,1629.92) ; v1@1247.35,1629.24 v1@1247.8,1628.8
  Bottom Layer w7.87: v2(114.17,1929.13) HDR_L1.21@173.23,1929.13
EXTEND_A11: HDR_L1.23 U4.K3 | length 1191.3
  Top Layer w5: v2@112.29,1897.5 113.08,1897.5 180.06,1897.5 297.86,1779.7 503.93,1779.7 517.32,1793.09 809.27,1793.09 954.33,1648.03 v1@957.48,1644.88 ; v1(1090.55,1629.92) U4.K3@1110.24,1610.24
  MidLayer3 w5: v1(954.72,1648.43) 966.08,1637.07 1075.62,1637.07 1082.77,1629.92 v1(1090.55,1629.92)
  Bottom Layer w7.87: v2@114.17,1897.64 HDR_L1.23@173.23,1897.64
  other v2: 113.08,1898.29
EXTEND_A12: HDR_L1.25 U4.K5 | length 1274.9
  Top Layer w5: v2@114.26,1867.56 128.05,1867.56 278.16,1717.45 619.3,1717.45 v1(644.52,1742.66) ; v1(1169.29,1629.92) U4.K5@1188.98,1610.24
  MidLayer3 w5: v1(644.52,1742.66) 667.15,1720.03 861.98,1720.03 892.94,1689.08 1102.41,1689.08 1110.69,1680.8 1110.69,1657.56 1118.57,1649.68 1144.96,1649.68 1164.72,1629.92 v1(1169.29,1629.92)
  Bottom Layer w7.87: v2(114.17,1866.14) HDR_L1.25@173.23,1866.14
EXTEND_A13: HDR_L1.27 U4.L3 | length 1187.7
  Top Layer w5: v2(114.17,1834.65) 119.59,1834.65 247.04,1707.2 603.23,1707.2 684.86,1625.57 910.2,1625.57 944.64,1591.13 v1(965.3,1591.13) v1@964.32,1590.14 ; v1(1090.55,1590.55) U4.L3@1110.24,1570.87
  MidLayer4 w5: v1@965.3,1590.16 966.27,1590.16 v1(965.3,1591.13) 988.92,1614.74 1059.77,1614.74 1083.96,1590.55 v1(1090.55,1590.55)
  Bottom Layer w7.87: v2(114.17,1834.65) HDR_L1.27@173.23,1834.64
EXTEND_A14: HDR_L1.29 U4.M5 | length 1314.6
  Top Layer w5: v2(114.17,1803.15) 125.09,1803.15 231.52,1696.71 580.26,1696.71 707.5,1569.48 756.7,1569.48 v1(757.68,1570.46) ; v1(1169.29,1551.18) U4.M5@1188.98,1531.5
  MidLayer4 w5: v1(757.68,1570.46) 783.26,1544.88 783.26,1527.17 808.85,1501.58 846.24,1501.58 895.44,1550.78 1035.17,1550.78 1054.46,1531.5 1139.76,1531.5 1159.45,1551.18 v1(1169.29,1551.18)
  Bottom Layer w7.87: v2(114.17,1803.15) HDR_L1.29@173.23,1803.15
EXTEND_A15: HDR_L1.31 U4.M4 | length 1234.9
  Top Layer w5: v2(114.17,1771.65) 121.91,1771.65 278.95,1614.61 623,1614.61 690.77,1546.85 793.1,1546.85 v1(815.74,1524.22) ; v1(1129.92,1551.18) U4.M4@1149.61,1531.5
  MidLayer4 w5: v1(815.74,1524.22) 862.39,1570.87 1114.17,1570.87 1129.92,1555.12 v1(1129.92,1551.18)
  Bottom Layer w7.87: v2(114.17,1771.65) HDR_L1.31@173.23,1771.65
EXTEND_A16: HDR_L1.33 U4.M6 | length 1337.1
  Top Layer w5: v2(114.17,1740.16) 121.1,1740.16 259.25,1602 613.38,1602 690.19,1525.2 v1(757.68,1525.2) ; v1(1208.66,1551.18) U4.M6@1228.35,1531.5
  MidLayer4 w5: v1(757.68,1525.2) 758.66,1525.2 796.06,1487.81 857.06,1487.81 874.78,1505.52 1007.62,1505.52 1022.42,1490.72 1141.51,1490.72 1150,1499.21 1150,1520.87 1160.24,1531.1 1188.58,1531.1 v1(1208.66,1551.18)
  Bottom Layer w7.87: v2(114.17,1740.16) HDR_L1.33@173.23,1740.15
EXTEND_A17: HDR_L1.35 U4.N6 | length 1286.2
  Top Layer w5: v2(114.17,1708.66) 251.96,1570.88 507.87,1570.88 536.63,1542.12 649.44,1542.12 687.02,1504.54 966.29,1504.54 v1(983.02,1484.86) ; v1(1208.66,1511.81) U4.N6@1228.35,1492.13
  MidLayer3 w5: v1(983.02,1484.86) 1181.7,1484.86 v1(1208.66,1511.81)
  Bottom Layer w7.87: v2(114.17,1708.66) HDR_L1.35@173.23,1708.66
EXTEND_A18: HDR_L1.37 U4.N1 | length 1078.6
  Top Layer w5: v2(114.17,1677.17) 270.5,1520.84 646.49,1520.84 675.2,1492.13 784.85,1492.13 815.74,1461.24 1000.61,1461.24 U4.N1@1031.5,1492.13
  Bottom Layer w7.87: v2(114.17,1677.17) HDR_L1.37@173.23,1677.16
EXTEND_A19: HDR_L1.39 U4.P2 | length 1115.6
  Top Layer w5: v2(114.17,1645.67) 250.82,1509.02 ; 249.34,1510.5 251.57,1508.27 641.57,1508.27 669.9,1479.94 775.39,1479.94 804.91,1450.42 1001.85,1450.42 1002.67,1451.24 1004.75,1451.24 1025.44,1471.93 1051.69,1471.93 U4.P2@1070.87,1452.76
  Bottom Layer w7.87: v2(114.17,1645.67) HDR_L1.39@173.23,1645.67
EXTEND_A20: HDR_L1.41 U4.P7 | length 1328.4
  Top Layer w5: v2@113.08,1614.61 113.84,1613.85 234.43,1493.26 638.74,1493.26 686.33,1445.67 714.06,1417.94 v1(758.66,1417.94) ; v1(1248.03,1433.07) U4.P7@1267.72,1452.76
  MidLayer3 w5: v1(758.66,1417.94) 940,1417.94 974.97,1452.91 1232.2,1452.91 1248.03,1437.08 v1(1248.03,1433.07)
  Bottom Layer w7.87: v2(114.17,1614.17) HDR_L1.41@173.23,1614.17
EXTEND_A21: HDR_L1.43 U4.R2 | length 1102.5
  Top Layer w5: v2(114.17,1582.68) 160.35,1536.5 217.77,1479.08 629.22,1479.08 714.63,1393.66 1054.76,1393.66 U4.R2@1072.13,1411.02
  Bottom Layer w7.87: v2(114.17,1582.68) HDR_L1.43@173.23,1582.67
EXTEND_A22: HDR_L1.45 U4.R4 | length 1185.9
  Top Layer w5: v1(1129.92,1393.7) U4.R4@1149.61,1413.39
  MidLayer1 w5: v2(114.17,1551.18) 171.64,1493.71 633.7,1493.71 748.41,1379 1028.34,1379 1033.07,1374.27 1113.84,1374.27 1129.92,1390.35 v1(1129.92,1393.7)
  Bottom Layer w7.87: v2(114.17,1551.18) HDR_L1.45@173.23,1551.18
EXTEND_A23: HDR_L1.47 U4.T3 | length 1176.1
  Top Layer w5: v1(1090.55,1354.33) U4.T3@1110.24,1374.02
  MidLayer1 w5: v2(114.17,1519.69) 155.93,1477.93 630.78,1477.93 789.17,1319.54 920.04,1319.54 938.74,1300.85 1028.28,1300.85 1077.48,1350.05 ; 1077.44,1350.09 1081.68,1354.33 v1(1090.55,1354.33)
  Bottom Layer w7.87: v2(114.17,1519.69) HDR_L1.47@173.23,1519.68
EXTEND_A24: HDR_L1.49 U4.D6 | length 1366
  Top Layer w5: v1@1208.66,1866.14 U4.D6@1228.35,1846.46
  MidLayer2 w5: v2(114.17,1488.19) 149.21,1488.19 520.47,1859.45 578.74,1859.45 589.37,1848.82 958.38,1848.82 979.48,1869.92 1002.91,1869.92 1026.16,1846.68 1189.2,1846.68 v1(1208.04,1865.52) v1@1208.66,1866.14
  Bottom Layer w7.87: v2(114.17,1488.19) HDR_L1.49@173.23,1488.19
EXTEND_A25: HDR_L1.51 U4.F7 | length 1388.4
  Top Layer w5: v1(1248.03,1787.4) U4.F7@1267.72,1767.72
  MidLayer2 w5: v2(114.17,1456.69) 145.67,1456.69 448.82,1759.84 484.46,1759.84 515.56,1790.94 516.35,1791.33 ; 515.76,1790.74 516.35,1791.33 ; v1@1248.03,1787.8 v1(1248.03,1787.4) 1228.11,1767.48 1081.33,1767.48 1053.94,1794.88 983.86,1794.88 975.59,1803.15 562.99,1803.15 551.18,1791.33 516.35,1791.33
  Bottom Layer w7.87: v2(114.17,1456.69) HDR_L1.51@173.23,1456.69
EXTEND_A26: HDR_L1.53 U4.G3 | length 1243.7
  Top Layer w5: v1(1091.38,1747.78) U4.G3@1110.24,1728.35
  MidLayer2 w5: v2(114.17,1425.2) 145.67,1425.2 418.72,1698.25 ; 418.03,1698.93 428.28,1709.17 543.31,1709.17 617.6,1783.46 942.13,1783.46 997.51,1728.08 1070.5,1728.08 1090.79,1748.37 v1@1091.38,1748.97
  Bottom Layer w7.87: v2(114.17,1425.2) HDR_L1.53@173.23,1425.19
EXTEND_A27: HDR_L1.55 U4.G4 | length 1303.4
  Top Layer w5: v1(1129.92,1748.03) U4.G4@1149.61,1728.35
  MidLayer2 w5: v1(114.96,1392.52) 116.14,1393.7 145.67,1393.7 448.81,1696.85 545.13,1696.85 621.74,1773.46 934.02,1773.46 1000.67,1706.81 1089.02,1706.81 1113.05,1730.84 ; 1113.09,1730.8 v1@1129.92,1747.64
  Bottom Layer w7.87: v1@114.96,1393.7 HDR_L1.55@173.23,1393.7
EXTEND_A28: HDR_L1.57 U4.J7 | length 1426
  Top Layer w5: v1(1248.03,1669.29) U4.J7@1267.72,1649.61
  MidLayer2 w5: v2(114.17,1362.21) 145.67,1362.21 440.94,1657.48 507.87,1657.48 519.69,1669.29 539.76,1669.29 633.94,1763.46 925.91,1763.46 1000.39,1688.98 1228.35,1688.98 v1(1248.03,1669.29)
  Bottom Layer w7.87: v2(114.17,1362.21) HDR_L1.57@173.23,1362.2
EXTEND_A29: HDR_L1.59 U4.J4 | length 1242.6
  Top Layer w5: v1(1130.78,1669.38) U4.J4@1149.61,1649.61
  MidLayer2 w5: v2(114.17,1330.71) 145.67,1330.71 437,1622.05 1052.72,1622.05 1080.35,1649.68 1111.1,1649.68 v1@1130.31,1668.9
  Bottom Layer w7.87: v2(114.17,1330.71) HDR_L1.59@173.23,1330.71
EXTEND_A30: HDR_L1.61 U4.L9 | length 1491.8
  Top Layer w5: U4.L9@1346.46,1570.87 1347.24,1570.87 v1@1367.32,1550.79
  MidLayer2 w5: v2(114.17,1299.21) 145.67,1299.21 452.96,1606.51 816.75,1606.51 852.38,1570.88 1347.23,1570.88 v1@1367.32,1550.79
  Bottom Layer w7.87: v2(114.17,1299.21) HDR_L1.61@173.23,1299.21
  other v1: 1365.35,1550.39
EXTEND_A31: HDR_L1.63 U4.M8 | length 1388.1
  Top Layer w5: v1(1287.4,1551.18) U4.M8@1307.09,1531.5
  MidLayer2 w5: v2(114.17,1267.72) 145.67,1267.72 403.4,1525.46 ; 403.74,1525.12 403.83,1525.2 406.78,1528.15 723.03,1528.15 742.71,1547.83 1063.11,1547.83 1079.45,1531.49 1267.71,1531.49 v1@1285.43,1549.21
  Bottom Layer w7.87: v2(114.17,1267.72) HDR_L1.63@173.23,1267.71
EXTEND_A32: HDR_L1.65 U4.M1 | length 1100.3
  Top Layer w5: v1@984.98,1523.23 993.25,1531.5 U4.M1@1031.5,1531.5
  MidLayer2 w5: v2(114.17,1236.22) 145.67,1236.22 413.98,1504.54 837.38,1504.54 858.05,1525.2 v1(983.02,1525.2) v1@984.98,1523.23
  Bottom Layer w7.87: v2(114.17,1236.22) HDR_L1.65@173.23,1236.22
EXTEND_A33: HDR_L1.67 U4.N2 | length 1150.5
  Top Layer w5: v1(1053.16,1510.2) 1053.16,1509.02 1070.06,1492.13 U4.N2@1070.87,1492.13
  MidLayer2 w5: v2(114.17,1204.72) 145.67,1204.72 421.26,1480.32 433.07,1492.13 950.93,1492.13 963.34,1504.54 1047.5,1504.54 v1(1053.16,1510.2)
  Bottom Layer w7.87: v2(114.17,1204.72) HDR_L1.67@173.23,1204.72
EXTEND_A34: HDR_L1.69 U4.P3 | length 1217.3
  Top Layer w5: v1(1090.55,1433.07) U4.P3@1110.24,1452.76
  MidLayer2 w5: v2(114.17,1173.23) 145.67,1173.23 440.94,1468.5 441.73,1468.5 451.74,1478.51 684.32,1478.51 725.21,1437.62 946.93,1437.62 957.43,1448.13 1075.49,1448.13 v1(1090.55,1433.07)
  Bottom Layer w7.87: v2(114.17,1173.23) HDR_L1.69@173.23,1173.23
EXTEND_A35: HDR_L1.71 U4.P9 | length 1479.8
  Top Layer w5: v1(1326.77,1433.07) U4.P9@1346.46,1452.76
  MidLayer2 w5: v2(114.17,1141.73) 145.67,1141.73 448.81,1444.88 507.87,1444.88 519.68,1433.07 550,1433.07 587.4,1395.67 925.99,1395.67 968.11,1437.79 1058.27,1437.79 1082.67,1413.39 1307.09,1413.39 v1@1325.79,1432.09
  Bottom Layer w7.87: v2(114.17,1141.73) HDR_L1.71@173.23,1141.73
EXTEND_A36: HDR_L1.73 U4.R1 | length 1131.2
  Top Layer w5: v1(990.2,1416.46) 993.27,1413.39 U4.R1@1031.5,1413.39
  MidLayer2 w5: v2(114.17,1110.24) 145.67,1110.24 440.94,1405.51 507.87,1405.51 516.14,1413.78 535.43,1413.78 564.72,1384.49 958.9,1384.49 990.53,1416.12 v1@992.13,1417.72
  Bottom Layer w7.87: v2(114.17,1110.24) HDR_L1.73@173.23,1110.23
EXTEND_A37: HDR_L1.75 U4.R9 | length 1452.2
  Top Layer w5: v1(1326.77,1393.7) U4.R9@1346.46,1413.39
  MidLayer2 w5: v2(114.17,1078.74) 145.67,1078.74 448.81,1381.89 507.87,1381.89 520.03,1369.73 972.88,1369.73 992.13,1388.98 1056.19,1388.98 1070.89,1374.27 1307.34,1374.27 v1(1326.77,1393.7)
  Bottom Layer w7.87: v2(114.17,1078.74) HDR_L1.75@173.23,1078.74
EXTEND_A38: HDR_L1.77 U4.V1 | length 1104.1
  Top Layer w5: v1(952.69,1324.63) 982.04,1295.28 U4.V1@1031.5,1295.28
  MidLayer2 w5: v2(114.17,1047.24) 145.67,1047.24 329.88,1231.46 460,1231.46 521.52,1292.98 826.56,1292.98 859.03,1325.45 951.87,1325.45 v1(952.69,1324.63)
  Bottom Layer w7.87: v2(114.17,1047.24) HDR_L1.77@173.23,1047.24
EXTEND_A39: HDR_L1.79 U4.T9 | length 1496.2
  Top Layer w5: U4.T9@1346.46,1374.02 1346.85,1374.02 v1(1366.54,1393.7)
  MidLayer2 w5: v2(114.17,1015.75) 145.67,1015.75 343.19,1213.27 504.79,1213.27 553.01,1261.49 999.68,1261.49 1072.83,1334.64 1307.48,1334.64 v1(1366.54,1393.7)
  Bottom Layer w7.87: v2(114.17,1015.75) HDR_L1.79@173.23,1015.74
EXTEND_A40: HDR_L1.81 U4.V6 | length 1312
  Top Layer w5: v1(1208.66,1275.59) U4.V6@1228.35,1295.28
  MidLayer2 w5: v2(114.17,984.25) 145.67,984.25 358.68,1197.26 503.64,1197.26 515.58,1185.32 533.35,1185.32 570.92,1222.89 582.77,1234.73 1096.66,1234.73 1117.82,1255.9 1177.48,1255.9 1197.16,1275.59 v1(1208.66,1275.59)
  Bottom Layer w7.87: v2(114.17,984.25) HDR_L1.81@173.23,984.25
EXTEND_A41: HDR_L1.83 U4.W4 | length 1220
  Top Layer w5: v1(1129.92,1236.22) U4.W4@1149.61,1255.91
  MidLayer2 w5: v2(114.17,952.76) 145.67,952.75 268.23,1075.31 ; 268.31,1075.23 280.92,1087.83 442.07,1087.83 517.72,1163.48 531.1,1163.48 588.76,1221.14 1114.84,1221.14 v1(1129.92,1236.22)
  Bottom Layer w7.87: v2(114.17,952.76) HDR_L1.83@173.23,952.75
EXTEND_A42: HDR_L1.85 U4.Y2 | length 1146.4
  Top Layer w5: v1(964.91,1186.73) 986.18,1208 1008.64,1208 1017.31,1199.34 1025.94,1199.34 1025.58,1198.98 1046.1,1198.98 ; 1046.46,1198.94 1054.18,1198.94 1070.87,1215.63 U4.Y2@1070.87,1216.54
  MidLayer2 w5: v2(114.17,921.26) 314.5,921.26 478.32,1085.08 502.35,1085.08 522.8,1105.52 558.42,1105.52 639.62,1186.73 v1(964.91,1186.73)
  Bottom Layer w7.87: v2(114.17,921.26) HDR_L1.85@173.23,921.26
EXTEND_A43: HDR_L1.87 U4.AD1 | length 1064.6
  Top Layer w5: v1(989.84,1055.59) 993.31,1059.05 U4.AD1@1031.5,1059.05
  MidLayer2 w5: v2(114.17,889.76) 397.26,889.76 468.07,960.57 503.93,960.57 620.83,1077.48 967.95,1077.48 v1(989.84,1055.59)
  Bottom Layer w7.87: v2(114.17,889.76) HDR_L1.87@173.23,889.76
EXTEND_A44: HDR_L1.89 U4.J5 | length 1878
  Top Layer w5: v1(1169.29,1669.29) U4.J5@1188.98,1649.61
  MidLayer3 w5: v2(114.17,858.27) 133.86,858.27 168.4,892.81 168.4,1435.11 433.01,1699.72 555.23,1699.72 624.25,1768.74 901.45,1768.74 970.47,1699.72 1133.14,1699.72 1163.57,1669.29 v1(1169.29,1669.29)
  Bottom Layer w7.87: v2(114.17,858.27) HDR_L1.89@173.23,858.26
EXTEND_A45: HDR_L1.91 U4.K2 | length 1650.7
  Top Layer w5: v1(906.3,1649.61) 927.95,1627.95 1055,1627.95 1070.87,1612.09 U4.K2@1070.87,1610.24
  MidLayer3 w5: v2(114.17,826.77) 133.86,826.77 192.91,885.83 192.91,1358.27 460.63,1625.99 543.7,1625.99 567.39,1649.68 v1@906.3,1649.68
  Bottom Layer w7.87: v2(114.17,826.77) HDR_L1.91@173.23,826.77
EXTEND_A46: HDR_L1.93 U4.L7 | length 1855.8
  Top Layer w5: v1(1248.03,1590.55) U4.L7@1267.72,1570.87
  MidLayer3 w5: v2(114.17,795.28) 133.86,795.28 216.54,877.95 216.54,1350.39 386.09,1519.95 478.35,1612.2 549.61,1612.2 562.81,1625.41 1065.57,1625.41 1080.74,1610.24 1228.35,1610.24 v1(1248.03,1590.55)
  Bottom Layer w7.87: v2(114.17,795.28) HDR_L1.93@173.23,795.27
EXTEND_A47: HDR_L1.95 U4.M7 | length 1840
  Top Layer w5: v1(1248.03,1551.18) U4.M7@1267.72,1531.5
  MidLayer3 w5: v2(114.17,763.78) 133.86,763.78 240.16,870.08 240.16,1342.52 425.79,1528.15 516.8,1528.15 534.51,1545.86 830.5,1545.86 855.5,1570.87 1228.35,1570.87 v1(1248.03,1551.18)
  Bottom Layer w7.87: v2(114.17,763.78) HDR_L1.95@173.23,763.78
EXTEND_A48: HDR_L1.97 U4.N5 | length 1765.1
  Top Layer w5: v1@1167.32,1511.42 v1(1170.47,1511.42) ; v1@1174.02,1511.42 v1(1170.47,1511.42) ; U4.N5@1188.98,1492.13 1188.98,1492.91 v1(1170.47,1511.42)
  MidLayer3 w5: v2(114.17,732.28) 133.86,732.28 263.78,862.2 263.78,1334.65 433.67,1504.54 1008.21,1504.54 1035.17,1531.5 1150.39,1531.5 v1(1170.47,1511.42)
  Bottom Layer w7.87: v2(114.17,732.28) HDR_L1.97@173.23,732.28
EXTEND_A49: HDR_L1.99 U4.P1 | length 1604.6
  Top Layer w5: v1@757.68,1456.32 777.4,1436.6 1015.34,1436.6 U4.P1@1031.5,1452.76
  MidLayer3 w5: v2(114.17,700.79) 133.86,700.79 287.4,854.33 287.4,1334.65 434.19,1481.44 733.54,1481.44 v1(756.7,1458.29)
  Bottom Layer w7.87: v2(114.17,700.79) HDR_L1.99@173.23,700.78
EXTEND_B0: HDR_L1.2 U4.B4 | length 959.6
  Top Layer w5: v2(500,2244.1) 1033.66,2244.09 1129.53,2148.22 1129.53,1945.28 U4.B4@1149.61,1925.2
  Bottom Layer w7.87: HDR_L1.2@440.94,2244.09 v2(500,2244.1)
EXTEND_B1: HDR_L1.4 U4.A3 | length 795.9
  Top Layer w5: v1(1090.55,1984.25) U4.A3@1108.66,1966.14
  MidLayer1 w5: v2(523.62,2212.6) 554.72,2243.7 796.46,2243.7 1056.3,1983.86 1090.16,1983.86 v1(1090.55,1984.25)
  Bottom Layer w7.87: HDR_L1.4@440.94,2212.6 v2(523.62,2212.6)
EXTEND_B2: HDR_L1.6 U4.B2 | length 752.9
  Top Layer w5: v1@1052.36,1906.69 U4.B2@1070.87,1925.2
  MidLayer1 w5: v2(500,2181.1) 524.41,2181.1 566.14,2139.37 663.78,2139.37 877.56,1925.59 897.64,1905.51 1052.36,1905.51 v1@1053.54,1905.51
  Bottom Layer w7.87: HDR_L1.6@440.94,2181.1 v2(500,2181.1)
  other v1: 1052.36,1906.55
EXTEND_B3: HDR_L1.8 U4.D3 | length 848.5
  Top Layer w5: U4.D3@1110.24,1847.64 v1(1129.13,1866.54)
  MidLayer1 w5: v2(523.62,2149.61) 546.85,2126.38 653.54,2126.38 893.7,1886.22 994.78,1886.22 1034.17,1846.83 1109.43,1846.83 v1(1129.13,1866.54)
  Bottom Layer w7.87: HDR_L1.8@440.94,2149.6 v2(523.62,2149.61)
EXTEND_B4: HDR_L1.10 U4.E1 | length 717
  Top Layer w5: v1(994.88,1816.65) 1003.7,1807.83 U4.E1@1029.41,1807.83
  MidLayer1 w5: v2(500,2118.11) 526.77,2118.11 536.62,2108.27 655.91,2108.27 947.52,1816.65 v1(994.88,1816.65)
  Bottom Layer w7.87: HDR_L1.10@440.94,2118.11 v2(500,2118.11)
EXTEND_B5: HDR_L1.12 U4.F3 | length 806.7
  Top Layer w5: v1(1090.55,1787.4) U4.F3@1110.24,1767.72
  MidLayer1 w5: v2(523.62,2086.62) 523.62,2077.56 541.73,2059.45 690.55,2059.45 955.12,1794.88 1083.07,1794.88 v1(1090.55,1787.4)
  Bottom Layer w7.87: HDR_L1.12@440.94,2086.61 v2(523.62,2086.62)
EXTEND_B6: HDR_L1.14 U4.G6 | length 970.3
  Top Layer w5: v1(1208.66,1748.03) U4.G6@1228.35,1728.35
  MidLayer1 w5: v2@500.39,2055.91 527.17,2055.91 534.88,2048.19 682.12,2048.19 1003.94,1726.38 1137.8,1726.38 1149.61,1738.19 1149.61,1761.26 1155.91,1767.56 1189.13,1767.56 v1(1208.66,1748.03)
  Bottom Layer w7.87: HDR_L1.14@440.94,2055.12 v2(500,2055.12)
EXTEND_B7: HDR_L1.16 U4.H7 | length 978.3
  Top Layer w5: v1(1248.03,1708.66) U4.H7@1267.72,1688.98
  MidLayer1 w5: v2(523.62,2023.62) 601.69,2023.62 775.31,1850 857.09,1850 992.91,1714.17 1146.46,1714.17 1160.63,1728.35 1229.53,1728.35 1248.62,1709.25 v1@1249.21,1708.66
  Bottom Layer w7.87: HDR_L1.16@440.94,2023.62 v2(523.62,2023.62)
EXTEND_B8: HDR_L1.18 U4.J9 | length 1084.1
  Top Layer w5: U4.J9@1346.46,1649.61 v1(1365.35,1668.5)
  MidLayer1 w5: v2@500,1991.73 613.9,1991.73 797.76,1807.87 877.21,1807.87 985.48,1699.61 1141.73,1699.61 1152.36,1688.98 1307.87,1688.98 1327.68,1669.17 ; 1328.35,1668.5 v1(1365.35,1668.5)
  Bottom Layer w7.87: HDR_L1.18@440.94,1992.12 v2(500,1992.13)
EXTEND_B9: HDR_L1.20 U4.H1 | length 760.3
  Top Layer w5: U4.H1@1031.99,1688.98 v1(1051.73,1669.23) v1@1052.37,1668.59
  MidLayer1 w5: v2(523.62,1960.63) 615.48,1960.63 778.87,1797.24 869.4,1797.24 997.41,1669.23 v1(1051.73,1669.23)
  Bottom Layer w7.87: HDR_L1.20@440.94,1960.63 v2(523.62,1960.63)
EXTEND_B10: HDR_L1.22 U4.K9 | length 1080.4
  Top Layer w5: U4.K9@1346.46,1610.24 1366.54,1630.32 v1@1367.72,1631.5
  MidLayer1 w5: v2(500,1929.14) 538.25,1929.14 538.74,1929.62 615,1929.62 759.19,1785.43 862.51,1785.43 998.34,1649.61 1307.88,1649.61 1312.99,1644.49 1327.56,1629.92 v1@1366.93,1629.92
  Bottom Layer w7.87: HDR_L1.22@440.94,1929.13 v2(500,1929.14)
  other v1: 1365.35,1629.13
EXTEND_B11: HDR_L1.24 U4.K6 | length 916.9
  Top Layer w5: v1(1208.66,1629.92) U4.K6@1228.35,1610.24
  MidLayer1 w5: v2@526.77,1898.03 608.22,1898.03 735.15,1771.1 859.82,1771.1 991.61,1639.3 1045.74,1639.3 1074.8,1610.24 1190.55,1610.24 v1@1207.09,1626.77
  Bottom Layer w7.87: HDR_L1.24@440.94,1897.64 v2(523.62,1897.64)
EXTEND_B12: HDR_L1.26 U4.K4 | length 824.2
  Top Layer w5: v1(1129.92,1629.92) U4.K4@1149.61,1610.24
  MidLayer3 w5: v1(723.24,1698.38) 750.76,1670.87 994.54,1670.87 1015.73,1649.68 1101.23,1649.68 1120.99,1629.92 v1(1129.92,1629.92)
  Bottom Layer w5: HDR_L1.26@438.92,1866.38 440.94,1866.38 578.39,1866.38 v1(723.24,1698.38)
EXTEND_B13: HDR_L1.28 U4.L4 | length 852.1
  Top Layer w5: v1(1129.92,1590.55) U4.L4@1149.61,1570.87
  MidLayer1 w5: v2@523.78,1834.49 v2(523.62,1834.65) 522.44,1835.83 523.62,1835.83 636.97,1835.83 844.45,1628.35 1041.34,1628.35 1070.47,1599.21 1070.47,1578.74 1078.35,1570.87 1114.17,1570.87 1129.92,1586.61 v1(1129.92,1590.55)
  Bottom Layer w7.87: HDR_L1.28@440.94,1834.64 v2(523.62,1834.65)
EXTEND_B14: HDR_L1.30 U4.M3 | length 799.1
  Top Layer w5: v1(1090.55,1551.18) U4.M3@1110.24,1531.5
  MidLayer1 w5: v2(500,1803.15) 653.9,1803.15 840.34,1616.71 1020.41,1616.71 1030.25,1606.87 1030.25,1579.79 1059.84,1550.2 1090.55,1550.2 v1@1091.54,1550.2
  Bottom Layer w7.87: HDR_L1.30@440.94,1803.15 v2(500,1803.15)
EXTEND_B15: HDR_L1.32 U4.M9 | length 1043.4
  Top Layer w5: v1(1326.77,1551.18) U4.M9@1346.46,1531.5
  MidLayer1 w5: v2@525.2,1771.66 659.81,1771.66 698.64,1732.82 698.64,1692.48 725.21,1665.91 766.54,1665.91 865.92,1566.53 1022.77,1566.53 1057.8,1531.5 1307.09,1531.5 v1(1326.77,1551.18)
  Bottom Layer w7.87: HDR_L1.32@440.94,1771.65 v2@523.62,1771.66
  other v2: 525.2,1771.82
EXTEND_B16: HDR_L1.34 U4.N7 | length 959.6
  Top Layer w5: v1(1248.03,1511.81) U4.N7@1267.72,1492.13
  MidLayer1 w5: v2(500,1740.16) 527.14,1713.02 554.7,1713.02 719.88,1547.83 839.35,1547.83 881.66,1505.52 1001.11,1505.52 1031.1,1475.53 1211.75,1475.53 v1(1248.03,1511.81)
  Bottom Layer w7.87: HDR_L1.34@440.94,1740.15 v2(500,1740.16)
EXTEND_B17: HDR_L1.36 U4.N4 | length 856
  Top Layer w5: v1(1129.92,1511.81) U4.N4@1149.61,1492.13
  MidLayer1 w5: v2@541.2,1738.73 542.18,1738.73 612.05,1738.73 735.05,1615.73 802.01,1615.73 864.98,1552.75 993.84,1552.75 1029.26,1517.33 1029.26,1499.82 1038.37,1490.72 1114.34,1490.72 1129.92,1506.3 v1(1129.92,1511.81)
  Bottom Layer w5: HDR_L1.36@439.7,1708.78 440.94,1708.78 513.38,1708.78 v2(542.18,1737.74)
EXTEND_B18: HDR_L1.38 U4.P4 | length 837.8
  Top Layer w5: v1(1129.92,1433.07) U4.P4@1149.61,1452.76
  MidLayer1 w5: v2@498.82,1675.98 498.82,1642.91 518.9,1622.83 ; 520.08,1622.44 587.79,1622.44 672.05,1538.18 672.05,1537.79 715.97,1493.87 827.38,1493.87 868.53,1452.72 1115.39,1452.72 1130.71,1437.4 v1@1130.71,1435.43
  Bottom Layer w7.87: HDR_L1.38@440.94,1677.16 v2(500,1677.17)
EXTEND_B19: HDR_L1.40 U4.P8 | length 962.4
  Top Layer w5: v1(1287.4,1433.07) U4.P8@1307.09,1452.76
  MidLayer1 w5: v2(523.62,1645.67) 588.19,1645.67 729.32,1504.54 835.92,1504.54 876.74,1463.71 1256.76,1463.71 v1(1287.4,1433.07)
  Bottom Layer w7.87: HDR_L1.40@440.94,1645.67 v2(523.62,1645.67)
